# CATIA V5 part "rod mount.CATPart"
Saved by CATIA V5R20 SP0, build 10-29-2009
Part number: rod mount 1
Source: Unknown
Bounding box of the stored display mesh (mm): x 0 to 15, y -10 to 58.3, z -46 to 0
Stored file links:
  C:\Users\Ikarus\OneDrive - FH JOANNEUM\BAC - Arbeit 1\CAD Modell\CAD-Modell-Step files\rod mount\rod mount.CATPart
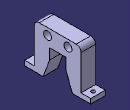
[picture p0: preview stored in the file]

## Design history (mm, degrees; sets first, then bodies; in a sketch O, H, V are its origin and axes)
Body1 (main body)
  Solid1 "Hauptkörper": solid without history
